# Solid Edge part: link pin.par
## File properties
Author: Robert a Rhodes jr
Template: Normal.par
Last saved by: Cadcim
Revision: 8
Application: Solid Edge
Accuracy: 0.99
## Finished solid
Body 1: solid body, 5 faces, 4 edges, 0 vertices.
  Faces by surface: plane 3, cylinder 2
  Edges by curve: circle 4
Bounding box of the edges (mm): 15.000 x 15.000 x 50.000, from (-7.5, -7.5, -22.7536) to (7.5, 7.5, 27.2464).
Cylindrical faces by radius (mm): R5 x1, R7.5 x1
Planar faces by outward normal: +z 1, -z 2
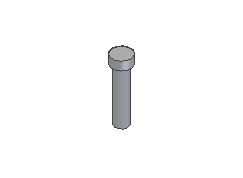
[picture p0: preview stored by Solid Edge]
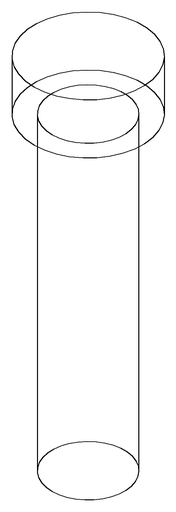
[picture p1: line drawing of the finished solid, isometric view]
